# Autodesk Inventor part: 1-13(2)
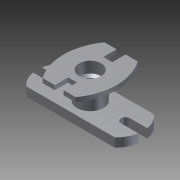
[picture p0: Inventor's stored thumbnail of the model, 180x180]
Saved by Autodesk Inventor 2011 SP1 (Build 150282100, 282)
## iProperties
Created: 2014-02
Part Number: 1-13(2)
Document SubType Name: Modeling
Designer: Administrator
Density: 1 g/cm^3
Author: Administrator
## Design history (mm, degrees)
sketch "草图1"
  geometry: L1 (-20, 8.944)-(20, 8.944); L2 (-20, -8.944)-(20, -8.944); L3 (-16, 2)-(-23.832, 2); L4 (-16, -2)-(-23.832, -2); L5 (16, 2)-(23.832, 2); L6 (16, -2)-(23.832, -2); A1 r 2 centre (-16, 0) between (-16, -2) and (-16, 2); A2 r 2 centre (16, 0) between (16, 2) and (16, -2); A3 r 12 centre (12, 0) between (20, -8.944) and (23.832, -2); A4 r 12 centre (12, 0) between (23.832, 2) and (20, 8.944); A5 r 12 centre (-12, 0) between (-20, 8.944) and (-23.832, 2); A6 r 12 centre (-12, 0) between (-23.832, -2) and (-20, -8.944); 1 further point
  constraints: 12 end point, 12 point on circle, 6 centre point, 5 parallel, 4 tangent, 1 horizontal
extrude "拉伸1" new body sketch "草图1" distance "d0" = 4; taper "d1" = 0 deg
sketch "草图2"
  geometry: C1 r 6 at (0, 0); 1 further point
  constraints: 1 centre point, 1 coincident
extrude "拉伸2" join sketch "草图2" distance "d2" = 10; taper "d3" = 0 deg
sketch "草图3"
  geometry: L1 (-2, -14)-(-2, -8); L2 (-2, -8)-(2, -8); L3 (2, -8)-(2, -14); L4 (-2, 14)-(-2, 8); L5 (-2, 8)-(2, 8); L6 (2, 8)-(2, 14); L7 (-7.494, 14)-(-2, 14); L8 (2, 14)-(7.494, 14); L9 (-7.494, -14)-(-2, -14); L10 (2, -14)-(7.494, -14); A1 r 12 centre (-12, 0) between (-20, 8.944) and (-23.832, 2) reference; A2 r 12 centre (12, 0) between (20, -8.944) and (23.832, -2) reference; A3 r 24 centre (12, 0) between (-7.494, 14) and (-7.494, -14); A4 r 24 centre (-12, 0) between (7.494, -14) and (7.494, 14)
  constraints: 20 end point, 8 perpendicular, 6 point on circle, 5 parallel, 2 centre point, 2 coincident, 2 horizontal
extrude "拉伸3" join sketch "草图3" distance "d4" = 2; taper "d5" = 0 deg
sketch "草图4"
  geometry: C1 r 5 at (0, 0); 1 further point
  constraints: 1 centre point, 1 coincident
extrude "拉伸4" cut sketch "草图4" distance "d6" = 6; taper "d7" = 0 deg
chamfer "倒角1" distance "d8" = 1; stored, may be unused: second distance "d9" = 2, angle "d10" = 45 deg
sketch "草图5"
  geometry: C1 r 4 at (0, 0) reference; C2 r 4 at (0, 0)
  constraints: 1 centre point, 1 coincident, 1 concentric
extrude "拉伸5" cut sketch "草图5" stored distance "d11" = 6; taper "d12" = 0 deg
node "实体1"
